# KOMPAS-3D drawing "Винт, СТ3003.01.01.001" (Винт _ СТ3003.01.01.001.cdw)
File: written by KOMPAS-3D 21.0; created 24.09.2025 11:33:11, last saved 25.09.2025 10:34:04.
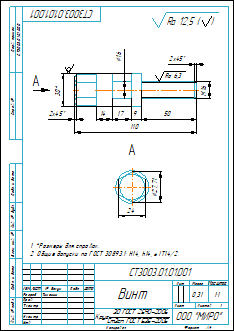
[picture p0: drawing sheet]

Sheet 1: A4, portrait

Document properties: Знак неуказанной шероховатости: 4; Параметр неуказанной шероховатости: Ra 12,5; Масса: 0.311599; L: 110; Полное имя файла: ..\..\3D\Кронштейн _ СТ3003.01.01.000\Винт _ СТ3003.01.01.001.m3d

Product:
- Part/product: Винт  | designation СТ3003.01.01.001
    Материал: Круг$d30 ГОСТ 2590-2006;Ст3сп ГОСТ 535-2005$ (density 7850 kg/m3)
    Масса: 0.311599
    additional columns: 110

Title block, sheet 1: Наименование: Винт; designation: СТ3003.01.01.001; Материал: Круг 30 ГОСТ 2590-2006 Ст3сп ГОСТ 535-2005; Масса: 0,31; Количество листов документа: 1; organisation: ООО "МИРО"; Форматы листов документа: A4; stored path: C:\Users\1\Yandex.Disk\Документы\Новая папка\Стапель №2\Стапель _ СТ3003.00.00.000\Опора _ СТ3003.01.00.000\2D\Кронштейн _ СТ3003.01.01.000\Винт _ СТ3003.01.01.001.cdw; Разработал: Тимонин

Views: Вид 1, Спереди, Вид по стрелке 2, Вид по стрелке А
Referenced files in C:\Users\1\Yandex.Disk\Документы\Новая папка\Стапель №2\Стапель _ СТ3003.00.00.000\Опора _ СТ3003.01.00.000\3D\Кронштейн _ СТ3003.01.01.000\: Винт _ СТ3003.01.01.001.m3d
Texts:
  Ra 6,3
  Ra 12,5
  Ra 12,5 ( )
  СТ3003.01.01.000
  СТ3003.01.01.001 Винт
Dimensions and other numbers on the sheet: 110; 50; 16; 2; 9; 17; 14; 30; 24; 27,71; 1:1; 1; 0,31

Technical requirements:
  *Размеры для справок.
  Общие допуски по ГОСТ 30893.1: Н14, h14, ± IT14/2.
